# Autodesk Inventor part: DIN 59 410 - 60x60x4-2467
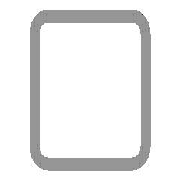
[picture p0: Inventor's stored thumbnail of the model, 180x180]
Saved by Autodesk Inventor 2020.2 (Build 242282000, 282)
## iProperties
Manager: www.cadconsulting.pl
Company: Fabian Stasiak CAD Consulting
IsCustomPart: 1
_CCFamilyMember: 60
_CCFamilyDisplayName: DIN 59410 (Kwadrat) - Rurki stalowe o przekroju kwadratowym formowane na gorąco
_FrameMemberDoc: Frame Member File
_Version: 15.0.0
_GetPNFromCC: 1
Created: 2014-02
Part Number: DIN 59 410 - 60x60x4-2467
Material: Stal, miękka
Description: Rurki stalowe o przekroju kwadratowym formowane na gorąco
Document SubType Name: Modellieren
Standard: DIN
Designer: F.Stasiak
Standards Organization: DIN
Language: pl-PL
Size Designation: 60x60x4
Categories: <MemberInstance><Categories><Category DisplayName="Kształtowniki konstrukcyjne" InternalName="089c4875-fa83-4c05-b084-43b9cc11f5ed" Mnemonic="GRDR"><CategoryPar
Stock Number: 60x60x4
Density: 7.85 g/cm^3
Appearance: Częściowo polerowana
Mass: 23928.9 g
Surface Area: 12217.8 cm^2
Volume: 3048.27 cm^3
Catalog Web Link: www.expertbooks.pl
G_L: 2467,000 mm
G_W: 60,000 mm
G_H: 60,000 mm
+E70408FA-FDA4-4C49-BBCF-49C8CB412972+CUTDETAIL1: Wytnij
Author: F.Stasiak
Subject: Zbiór ćwiczeń. Autodesk Inventor 2020. Kurs Professional
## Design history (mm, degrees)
node "Płaszczyzna początkowa"
node "Płaszczyzna końcowa"
sketch "Szkic1"
  geometry: L1 (-22, 30)-(22, 30); L2 (30, 22)-(30, -22); L3 (22, -30)-(-22, -30); L4 (-30, -22)-(-30, 22); L5 (-51.899, 0)-(51.899, 0) reference; L6 (0, -51.899)-(0, 51.899) reference; L7 (-22, 26)-(22, 26); L8 (26, 22)-(26, -22); L9 (22, -26)-(-22, -26); L10 (-26, -22)-(-26, 22); A1 r 8 centre (-22, 22) between (-22, 30) and (-30, 22); A2 r 8 centre (22, 22) between (30, 22) and (22, 30); A3 r 8 centre (22, -22) between (22, -30) and (30, -22); A4 r 8 centre (-22, -22) between (-30, -22) and (-22, -30); A5 r 4 centre (-22, 22) between (-22, 26) and (-26, 22); A6 r 4 centre (22, 22) between (26, 22) and (22, 26); A7 r 4 centre (22, -22) between (22, -26) and (26, -22); A8 r 4 centre (-22, -22) between (-26, -22) and (-22, -26); 3 further points
  constraints: 16 end point, 16 point on circle, 8 centre point, 8 tangent, 6 point on line, 4 parallel, 3 equal radius, 3 perpendicular, 1 horizontal, 7 other
  dimensions: "b" = 60 distance of point (-30, 30) point (30, 30); "msp_r" = 8 radius of A1 (= 2 x ParT); "d8" = 30 distance between parallel lines of L4 L6 (= d9); "d9" = 30 distance between parallel lines of L3 L5 (= 0.5 x b); "d10" = 4 distance between parallel lines of L3 L9 (= ParT)
extrude "Bryła" new body sketch "Szkic1" taper "d4" = 0 deg; stored distance "NLG" = 10
node "Driven Length"
  sketch "Sketch2"
    geometry: L1 (0, 0)-(10, 0) reference
    constraints: 2 end point, 1 horizontal
  workplane "Work Plane3"
  sketch "Sketch3"
    geometry: L1 (-2, 0)-(12, 0) reference; L2 (-2, 2467)-(12, 2467) reference
    dimensions: "d14" = 2467 distance between parallel lines of L1 L2 (derived)
node "Płaszczyzna konstrukcyjna4"
feature "Podział1"
body "Solid1"
other parameters: "ParT" = 4, "G_OFFSET_START" = 0 [user parameter; used in 1 equation term], "G_OFFSET_END" = -33 [user parameter; used in 1 equation term], "d11" = 0 (computed from G_OFFSET_START), "d12" = 2467 (= G_OFFSET_END + B_L), "G_L" = 2467 (= d14) [user parameter], "d13" = 90 deg
